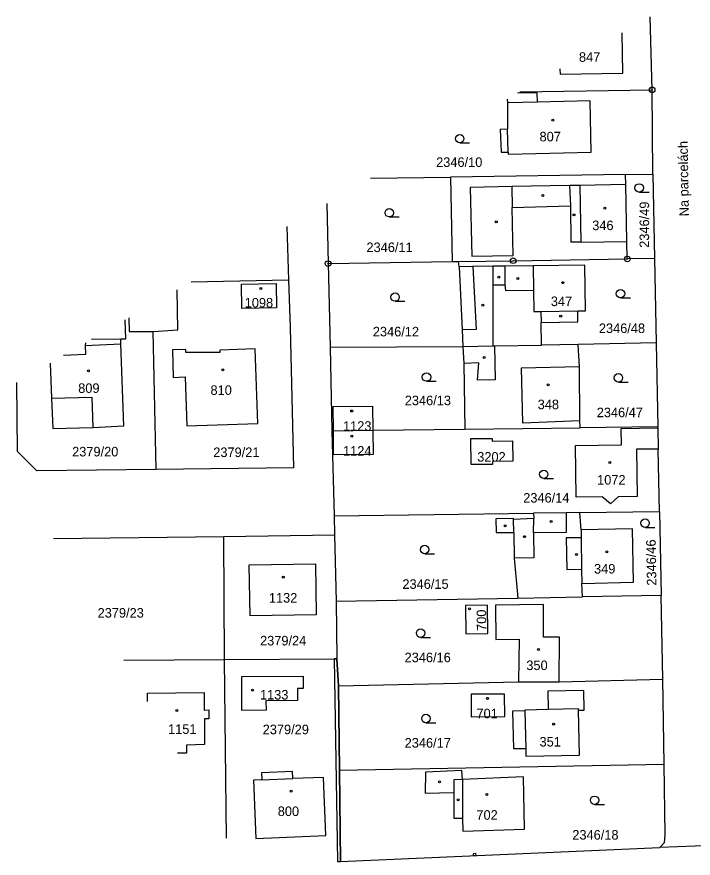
# Model space of a CAD drawing. Extents: x -758836 to -757729, y -1175316 to -1174366.
# Drawn here: x -758836.1 to -758715.8, y -1174936.9 to -1174787.2 of the extents above; entities that cross this region are included whole.
import ezdxf

# ---------------------------------------------------------------- set-up
doc = ezdxf.new("R2010")
doc.units = 0
for name, color, linetype in [('Hranice parcel', 7, 'Continuous'), ('Parcelní čísla', 7, 'Continuous'), ('Pop  PČ popisy', 7, 'Continuous'), ('Vnitřní kresba', 7, 'Continuous'), ('Věcná břemena k části', 7, 'Continuous'), ('Značky bodu BP', 7, 'Continuous'), ('Značky budov', 7, 'Continuous'), ('Značky kultur', 7, 'Continuous')]:
    doc.layers.add(name, color=color, linetype=linetype)

msp = doc.modelspace()

# ---------------------------------------------------------------- linework, layer by layer
at = {"layer": 'Hranice parcel'}
for p, q in [((-758723.09, -1174800.23), (-758723.47, -1174787.24)), ((-758746.62, -1174800.6), (-758723.09, -1174800.23)), ((-758722.95, -1174815.23), (-758723.09, -1174800.23)), ((-758773.2, -1174815.95), (-758758.95, -1174815.75)), ((-758727.82, -1174815.3), (-758758.95, -1174815.75)), ((-758758.95, -1174815.75), (-758758.66, -1174830.78)), ((-758727.82, -1174815.3), (-758722.95, -1174815.23)), ((-758722.95, -1174815.23), (-758722.66, -1174830.22)), ((-758780.97, -1174820.44), (-758780.73, -1174831.13)), ((-758788.09, -1174824.55), (-758787.75, -1174834)), ((-758722.66, -1174830.22), (-758727.52, -1174830.3)), ((-758722.66, -1174830.22), (-758722.37, -1174845.24)), ((-758780.73, -1174831.13), (-758758.66, -1174830.78)), ((-758780.73, -1174831.13), (-758780.34, -1174845.99)), ((-758758.66, -1174830.78), (-758757.56, -1174830.77)), ((-758757.42, -1174831.68), (-758757.56, -1174830.77)), ((-758787.75, -1174834), (-758787.45, -1174842.48)), ((-758811.32, -1174867.74), (-758811.85, -1174843.2)), ((-758736.27, -1174845.5), (-758742.78, -1174845.62)), ((-758722.37, -1174845.24), (-758736.27, -1174845.5)), ((-758736.03, -1174849.48), (-758736.27, -1174845.5)), ((-758722.37, -1174845.24), (-758722.09, -1174860.16)), ((-758780.34, -1174845.99), (-758756.75, -1174845.87)), ((-758780.34, -1174845.99), (-758780.07, -1174860.85)), ((-758772.77, -1174860.76), (-758756.39, -1174860.57)), ((-758756.39, -1174860.57), (-758735.89, -1174860.32)), ((-758722.09, -1174860.16), (-758735.89, -1174860.32)), ((-758722.09, -1174860.37), (-758722.09, -1174860.16)), ((-758722.09, -1174860.37), (-758722.01, -1174864.11)), ((-758780.07, -1174860.85), (-758779.77, -1174860.85)), ((-758780.07, -1174860.85), (-758779.67, -1174875.98)), ((-758779.77, -1174860.85), (-758772.77, -1174860.76)), ((-758721.79, -1174875.22), (-758722.01, -1174864.11)), ((-758779.67, -1174875.98), (-758744.17, -1174875.51)), ((-758735.94, -1174875.41), (-758721.79, -1174875.22)), ((-758721.79, -1174875.22), (-758721.49, -1174890.19)), ((-758779.67, -1174875.98), (-758779.58, -1174879.39)), ((-758799.28, -1174879.69), (-758779.58, -1174879.39)), ((-758799.14, -1174901.53), (-758799.28, -1174879.69)), ((-758779.58, -1174879.39), (-758779.27, -1174891.16)), ((-758746.99, -1174890.62), (-758735.49, -1174890.42)), ((-758721.49, -1174890.19), (-758735.49, -1174890.42)), ((-758721.19, -1174905.07), (-758721.49, -1174890.19)), ((-758779.27, -1174891.16), (-758746.99, -1174890.62)), ((-758779.27, -1174891.16), (-758779.15, -1174901.44)), ((-758817.08, -1174901.67), (-758799.14, -1174901.53)), ((-758798.81, -1174933.31), (-758799.14, -1174901.53)), ((-758779.15, -1174901.44), (-758778.87, -1174906.24)), ((-758778.87, -1174906.24), (-758746.84, -1174905.5)), ((-758746.84, -1174905.5), (-758739.62, -1174905.55)), ((-758739.62, -1174905.55), (-758721.19, -1174905.07)), ((-758720.97, -1174920.18), (-758721.19, -1174905.07)), ((-758778.87, -1174906.24), (-758778.71, -1174921.21)), ((-758778.71, -1174921.21), (-758720.97, -1174920.18)), ((-758778.71, -1174921.21), (-758778.54, -1174937.47)), ((-758778.54, -1174937.47), (-758721.71, -1174934.99)), ((-758710.56, -1174934.59), (-758721.71, -1174934.99))]:
    msp.add_line(p, q, dxfattribs=at)
for points in [[(-758739.5, -1174796.49), (-758739.48, -1174797.44), (-758728.3, -1174797.25), (-758728.43, -1174790.1)], [(-758750.12, -1174807.25), (-758749.93, -1174811.3), (-758748.71, -1174811.32), (-758748.68, -1174811.66), (-758733.92, -1174811.29), (-758734.14, -1174802.17), (-758743.51, -1174802.41), (-758743.55, -1174800.75), (-758747.02, -1174800.83)], [(-758748.85, -1174801.89), (-758748.81, -1174802.54), (-758748.79, -1174807.23), (-758750.12, -1174807.25)], [(-758727.52, -1174830.3), (-758727.58, -1174827.19), (-758727.79, -1174817.07), (-758727.82, -1174815.3)], [(-758757.56, -1174830.77), (-758747.81, -1174830.62), (-758727.52, -1174830.3)], [(-758742.78, -1174845.62), (-758742.85, -1174841.61), (-758736.31, -1174841.49), (-758736.34, -1174839.54), (-758734.93, -1174839.51), (-758735.08, -1174831.4), (-758744.24, -1174831.52), (-758749.31, -1174831.58), (-758751.4, -1174831.6), (-758754.97, -1174831.65), (-758757.42, -1174831.68)], [(-758757.42, -1174831.68), (-758756.89, -1174842.94), (-758756.75, -1174845.87)], [(-758805.07, -1174834.35), (-758787.75, -1174834)], [(-758796.15, -1174834.77), (-758789.99, -1174834.64), (-758789.9, -1174838.99), (-758796.06, -1174839.11), (-758796.15, -1174834.77)], [(-758811.85, -1174843.2), (-758807.43, -1174842.89), (-758807.57, -1174835.79)], [(-758829.92, -1174855.05), (-758829.67, -1174860.49), (-758822.56, -1174860.27), (-758817.03, -1174860.01), (-758817.58, -1174845.43), (-758817.61, -1174844.51), (-758816.7, -1174844.49), (-758816.79, -1174841.11)], [(-758816.17, -1174840.76), (-758816.12, -1174843.2), (-758811.85, -1174843.2)], [(-758787.45, -1174842.48), (-758786.89, -1174867.47), (-758811.32, -1174867.74)], [(-758823.89, -1174845.22), (-758823.91, -1174845.67), (-758823.85, -1174847.32), (-758827.8, -1174847.47)], [(-758756.75, -1174845.87), (-758751.4, -1174845.78), (-758751.14, -1174845.77), (-758742.78, -1174845.62)], [(-758793.71, -1174846.31), (-758799.99, -1174846.54), (-758799.97, -1174846.93), (-758806.02, -1174846.96), (-758806.02, -1174846.41), (-758808.42, -1174846.46), (-758808.27, -1174851.36), (-758806.16, -1174851.28), (-758805.83, -1174860.01), (-758793.23, -1174859.55), (-758793.71, -1174846.31)], [(-758756.75, -1174845.87), (-758756.61, -1174848.91), (-758756.39, -1174860.57)], [(-758830.13, -1174848.82), (-758829.92, -1174855.05)], [(-758735.89, -1174860.32), (-758735.96, -1174859.06), (-758736.03, -1174849.48)], [(-758811.32, -1174867.74), (-758832.5, -1174867.97), (-758835.98, -1174864.56), (-758836.09, -1174852.26)], [(-758779.77, -1174860.85), (-758779.81, -1174856.56), (-758772.81, -1174856.5), (-758772.77, -1174860.76)], [(-758722.01, -1174864.11), (-758725.89, -1174864.14), (-758725.75, -1174872.55), (-758729.16, -1174872.6), (-758730.53, -1174873.84), (-758732.01, -1174872.64), (-758736.61, -1174872.7), (-758736.74, -1174863.47), (-758728.55, -1174863.36), (-758728.6, -1174860.45), (-758722.09, -1174860.37)], [(-758772.77, -1174860.76), (-758772.74, -1174865.1), (-758779.74, -1174865.15), (-758779.77, -1174860.85)], [(-758751.53, -1174862.71), (-758747.95, -1174862.66), (-758747.89, -1174866.28), (-758751.49, -1174866.32), (-758751.48, -1174866.86), (-758755.3, -1174866.88), (-758755.36, -1174862.22), (-758751.54, -1174862.21), (-758751.53, -1174862.71)], [(-758744.17, -1174875.51), (-758744.16, -1174876.44), (-758747.74, -1174876.67), (-758747.75, -1174876.47), (-758750.9, -1174876.51), (-758750.86, -1174878.98), (-758747.71, -1174878.94), (-758747.66, -1174883.53), (-758746.99, -1174890.62)], [(-758735.94, -1174875.41), (-758738.41, -1174875.44), (-758744.17, -1174875.51)], [(-758735.49, -1174890.42), (-758735.62, -1174888.06), (-758726.4, -1174887.78), (-758726.61, -1174878.29), (-758735.74, -1174878.49), (-758735.94, -1174875.41)], [(-758829.59, -1174880), (-758799.28, -1174879.69)], [(-758782.99, -1174884.52), (-758782.84, -1174893.61), (-758794.6, -1174893.79), (-758794.78, -1174884.71), (-758782.99, -1174884.52)], [(-758756.22, -1174896.98), (-758752.32, -1174896.92), (-758752.38, -1174891.89), (-758756.27, -1174891.93), (-758756.22, -1174896.98)], [(-758739.62, -1174905.55), (-758739.57, -1174897.59), (-758742.44, -1174897.57), (-758742.42, -1174891.78), (-758750.93, -1174891.86), (-758750.9, -1174897.97), (-758746.77, -1174897.95), (-758746.84, -1174905.5)], [(-758799.14, -1174901.53), (-758779.65, -1174901.44), (-758779.15, -1174901.44)], [(-758791.78, -1174908.9), (-758791.77, -1174910.58), (-758796.04, -1174910.6), (-758796.09, -1174904.6), (-758785.18, -1174904.49), (-758785.18, -1174906.69), (-758786.18, -1174906.7), (-758786.16, -1174908.87), (-758791.78, -1174908.9)], [(-758745.54, -1174918.76), (-758736.01, -1174918.54), (-758736.19, -1174910.59), (-758735.2, -1174910.58), (-758735.24, -1174907.05), (-758741.62, -1174907.18), (-758741.57, -1174910.45), (-758745.73, -1174910.55), (-758745.73, -1174910.7), (-758747.93, -1174910.75), (-758747.76, -1174917.4), (-758745.57, -1174917.35), (-758745.54, -1174918.76)], [(-758812.84, -1174909.01), (-758812.86, -1174907.52), (-758802.77, -1174907.44), (-758802.74, -1174910.55)], [(-758755.31, -1174907.72), (-758755.31, -1174911.73), (-758749.31, -1174911.7), (-758749.33, -1174907.69), (-758755.31, -1174907.72)], [(-758802.74, -1174910.55), (-758801.95, -1174910.53), (-758801.94, -1174912.09), (-758802.73, -1174912.13), (-758802.69, -1174916.69), (-758805.91, -1174916.79), (-758805.9, -1174918.2), (-758807.53, -1174918.22)], [(-758721.71, -1174934.99), (-758720.92, -1174934.1), (-758720.79, -1174932.73), (-758720.97, -1174920.18)], [(-758787.06, -1174921.48), (-758792.59, -1174921.72), (-758792.53, -1174922.98), (-758794.02, -1174923.04), (-758793.57, -1174933.38), (-758781.11, -1174932.84), (-758781.52, -1174922.51), (-758787.01, -1174922.74), (-758787.06, -1174921.48)], [(-758745.97, -1174922.41), (-758756.85, -1174922.88), (-758756.92, -1174921.29), (-758763.41, -1174921.57), (-758763.46, -1174925.35), (-758758.38, -1174925.18), (-758758.35, -1174929.77), (-758756.81, -1174929.76), (-758756.79, -1174932.1), (-758745.78, -1174931.71), (-758745.97, -1174922.41)]]:
    msp.add_lwpolyline(points, dxfattribs=at)
at = {"layer": 'Vnitřní kresba'}
for p, q in [((-758743.51, -1174802.41), (-758748.81, -1174802.54)), ((-758748.71, -1174811.32), (-758748.79, -1174807.23)), ((-758737.77, -1174817.25), (-758748.06, -1174817.44)), ((-758735.98, -1174817.22), (-758737.77, -1174817.25)), ((-758737.77, -1174817.25), (-758737.63, -1174820.86)), ((-758727.79, -1174817.07), (-758735.98, -1174817.22)), ((-758735.98, -1174817.22), (-758735.77, -1174827.3)), ((-758748.06, -1174817.44), (-758755.48, -1174817.57)), ((-758755.48, -1174817.57), (-758755.17, -1174829.83)), ((-758748.06, -1174817.44), (-758747.99, -1174821.13)), ((-758747.99, -1174821.13), (-758737.63, -1174820.86)), ((-758747.83, -1174829.7), (-758747.99, -1174821.13)), ((-758737.63, -1174820.86), (-758737.54, -1174827.33)), ((-758735.77, -1174827.3), (-758737.54, -1174827.33)), ((-758735.77, -1174827.3), (-758727.58, -1174827.19)), ((-758755.17, -1174829.83), (-758747.83, -1174829.7)), ((-758754.97, -1174831.65), (-758754.42, -1174842.83)), ((-758751.4, -1174831.6), (-758751.4, -1174834.88)), ((-758749.31, -1174831.58), (-758749.3, -1174834.88)), ((-758744.24, -1174831.52), (-758744.18, -1174835.85)), ((-758751.4, -1174834.88), (-758749.3, -1174834.88)), ((-758751.4, -1174834.88), (-758751.4, -1174845.78)), ((-758749.3, -1174834.88), (-758749.16, -1174835.91)), ((-758749.16, -1174835.91), (-758744.18, -1174835.85)), ((-758744.18, -1174835.85), (-758744.14, -1174839.67)), ((-758744.14, -1174839.67), (-758742.88, -1174839.65)), ((-758742.88, -1174839.65), (-758736.34, -1174839.54)), ((-758742.88, -1174839.65), (-758742.85, -1174841.61)), ((-758754.42, -1174842.83), (-758756.89, -1174842.94)), ((-758823.91, -1174845.67), (-758817.58, -1174845.43)), ((-758822.81, -1174844.59), (-758817.61, -1174844.51)), ((-758751.14, -1174845.77), (-758751.03, -1174851.8)), ((-758753.91, -1174848.79), (-758756.61, -1174848.91)), ((-758754.16, -1174851.86), (-758753.91, -1174848.79)), ((-758736.03, -1174849.48), (-758746.37, -1174849.74)), ((-758746.37, -1174849.74), (-758746.13, -1174859.43)), ((-758751.03, -1174851.8), (-758754.16, -1174851.86)), ((-758829.92, -1174855.05), (-758822.73, -1174854.91)), ((-758822.73, -1174854.91), (-758822.56, -1174860.27)), ((-758746.13, -1174859.43), (-758735.96, -1174859.06)), ((-758738.41, -1174875.44), (-758738.36, -1174878.97)), ((-758747.71, -1174878.94), (-758747.74, -1174876.67)), ((-758744.17, -1174879.04), (-758744.16, -1174876.44)), ((-758735.74, -1174878.49), (-758735.72, -1174879.88)), ((-758738.36, -1174878.97), (-758744.17, -1174879.04)), ((-758744.17, -1174879.04), (-758744.12, -1174883.49)), ((-758735.72, -1174879.88), (-758738.4, -1174879.92)), ((-758738.4, -1174879.92), (-758738.28, -1174885.53)), ((-758735.72, -1174879.88), (-758735.65, -1174885.5)), ((-758744.12, -1174883.49), (-758747.66, -1174883.53)), ((-758738.28, -1174885.53), (-758735.65, -1174885.5)), ((-758735.65, -1174885.5), (-758735.62, -1174888.06)), ((-758745.73, -1174910.7), (-758745.57, -1174917.35)), ((-758736.2, -1174910.33), (-758741.57, -1174910.45)), ((-758736.19, -1174910.59), (-758736.2, -1174910.33)), ((-758792.53, -1174922.98), (-758787.01, -1174922.74)), ((-758756.85, -1174922.88), (-758758.39, -1174922.95)), ((-758758.39, -1174922.95), (-758758.38, -1174925.18)), ((-758756.85, -1174922.88), (-758756.81, -1174929.76))]:
    msp.add_line(p, q, dxfattribs=at)
at = {"layer": 'Věcná břemena k části'}
for points in [[(-758779.65, -1174901.44), (-758779.04, -1174937.49), (-758778.54, -1174937.47), (-758778.71, -1174921.21), (-758778.87, -1174906.24), (-758779.15, -1174901.44)], [(-758754.9, -1174936.44), (-758754.39, -1174936.42), (-758754.45, -1174936.06), (-758754.94, -1174936.13)]]:
    msp.add_lwpolyline(points, close=True, dxfattribs=at)
at = {"layer": 'Značky bodu BP'}
for centre, radius in [((-758723.09, -1174800.23), 0.5), ((-758723.09, -1174800.23), 0.0303), ((-758780.73, -1174831.13), 0.5), ((-758747.81, -1174830.62), 0.5), ((-758747.81, -1174830.62), 0.0303), ((-758727.52, -1174830.3), 0.5), ((-758727.52, -1174830.3), 0.0303), ((-758780.73, -1174831.13), 0.0303)]:
    msp.add_circle(centre, radius, dxfattribs=at)
at = {"layer": 'Značky budov'}
for centre in [(-758740.74, -1174805.64), (-758742.54, -1174819.04), (-758731.5, -1174821.27), (-758736.99, -1174822.44), (-758750.81, -1174823.69), (-758750.35, -1174833.55), (-758746.96, -1174833.77), (-758738.97, -1174834.52), (-758792.71, -1174835.55), (-758753.19, -1174838.53), (-758739.36, -1174840.46), (-758752.96, -1174847.85), (-758823.36, -1174850.19), (-758799.46, -1174850.03), (-758741.58, -1174852.7), (-758776.53, -1174857.35), (-758776.49, -1174861.82), (-758730.61, -1174866.52), (-758741.06, -1174876.98), (-758749.22, -1174877.77), (-758745.82, -1174879.7), (-758736.53, -1174882.87), (-758731.17, -1174882.38), (-758788.69, -1174886.9), (-758755.57, -1174892.56), (-758743.29, -1174899.76), (-758794.18, -1174907.02), (-758752.4, -1174908.46), (-758807.65, -1174910.6), (-758740.61, -1174913.07), (-758760.89, -1174923.33), (-758787.29, -1174924.99), (-758757.61, -1174926.5), (-758752.51, -1174925.54)]:
    msp.add_circle(centre, 0.175, dxfattribs=at)
at = {"layer": 'Značky kultur'}
for p, q in [((-758757.31, -1174809.66), (-758755.56, -1174809.66)), ((-758725.4, -1174818.42), (-758723.65, -1174818.42)), ((-758769.84, -1174822.83), (-758768.09, -1174822.83)), ((-758768.81, -1174837.83), (-758767.06, -1174837.83)), ((-758728.72, -1174837.23), (-758726.97, -1174837.23)), ((-758763.23, -1174852.06), (-758761.48, -1174852.06)), ((-758729.1, -1174852.2), (-758727.35, -1174852.2)), ((-758742.37, -1174869.36), (-758740.62, -1174869.36)), ((-758724.35, -1174878.05), (-758722.6, -1174878.05)), ((-758763.55, -1174882.73), (-758761.8, -1174882.73)), ((-758764.27, -1174897.61), (-758762.52, -1174897.61)), ((-758763.32, -1174912.8), (-758761.57, -1174912.8)), ((-758733.33, -1174927.34), (-758731.58, -1174927.34))]:
    msp.add_line(p, q, dxfattribs=at)
for centre in [(-758757.31, -1174808.91), (-758725.4, -1174817.67), (-758769.84, -1174822.08), (-758768.81, -1174837.08), (-758728.72, -1174836.48), (-758763.23, -1174851.31), (-758729.1, -1174851.45), (-758742.37, -1174868.61), (-758724.35, -1174877.3), (-758763.55, -1174881.98), (-758764.27, -1174896.86), (-758763.32, -1174912.05), (-758733.33, -1174926.59)]:
    msp.add_circle(centre, 0.75, dxfattribs=at)

# ---------------------------------------------------------------- texts
at = {"layer": 'Parcelní čísla'}
for s, p in [('847', (-758736.11, -1174795.24)), ('807', (-758743.12, -1174809.39)), ('2346/10', (-758761.51, -1174813.94)), ('346', (-758733.75, -1174825.18)), ('2346/11', (-758773.9, -1174829.08)), ('1098', (-758795.56, -1174838.94)), ('347', (-758741.11, -1174838.69)), ('2346/12', (-758772.77, -1174844.08)), ('2346/48', (-758732.57, -1174843.48)), ('809', (-758825.17, -1174854.13)), ('810', (-758801.64, -1174854.48)), ('2346/13', (-758767.09, -1174856.32)), ('348', (-758743.45, -1174857.03)), ('2346/47', (-758732.95, -1174858.45)), ('1123', (-758778.07, -1174860.87)), ('2379/20', (-758826.25, -1174865.43)), ('1124', (-758778.07, -1174865.29)), ('2379/21', (-758801.15, -1174865.54)), ('3202', (-758754.2, -1174866.35)), ('1072', (-758732.88, -1174870.44)), ('2346/14', (-758746.02, -1174873.64)), ('349', (-758733.43, -1174886.26)), ('2346/15', (-758767.51, -1174888.98)), ('1132', (-758791.26, -1174891.43)), ('2379/23', (-758821.72, -1174894.1)), ('2379/24', (-758792.83, -1174899.05)), ('2346/16', (-758767.12, -1174902.03)), ('350', (-758745.47, -1174903.43)), ('1133', (-758792.84, -1174908.67)), ('701', (-758754.34, -1174912.01)), ('2379/29', (-758792.36, -1174914.84)), ('1151', (-758809.19, -1174914.78)), ('2346/17', (-758767.11, -1174917.22)), ('351', (-758743.12, -1174917.03)), ('800', (-758789.68, -1174929.39)), ('702', (-758754.35, -1174930.05)), ('2346/18', (-758737.29, -1174933.59))]:
    msp.add_text(s, height=1.7, dxfattribs=at).set_placement(p)
for s, rotation, p in [('2346/49', 90, (-758723.63, -1174828.32)), ('2346/46', 91, (-758722.32, -1174888.4)), ('700', 91, (-758752.56, -1174896.45))]:
    msp.add_text(s, height=1.7, rotation=rotation, dxfattribs=at).set_placement(p)
at = {"layer": 'Pop  PČ popisy'}
msp.add_text('Na parcelách', height=1.7, rotation=91, dxfattribs=at).set_placement((-758716.55, -1174822.7))

doc.saveas('drawing.dxf')
